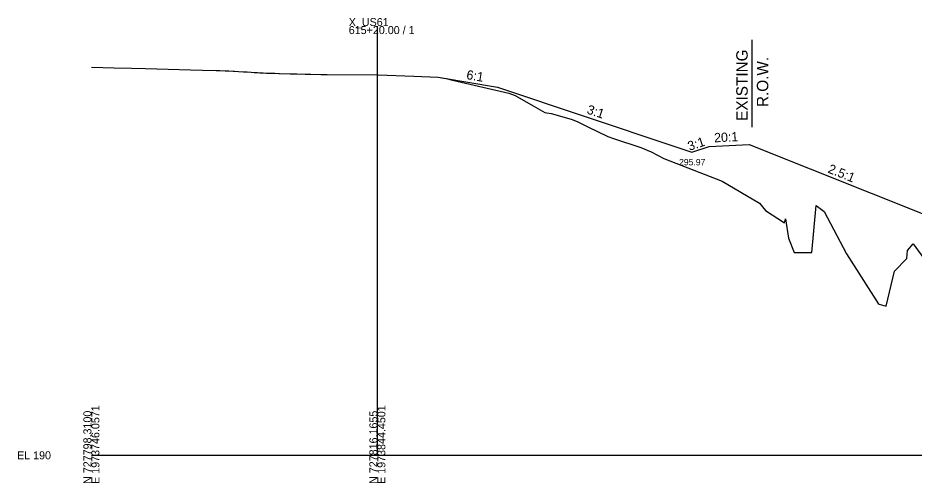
# Model space of a CAD drawing. Extents: x -26 to 1604, y -13 to 9623.
# Drawn here: x -25.7 to 287.7, y 7990.3 to 8152.8 of the extents above; entities that cross this region are included whole.
import ezdxf

# ---------------------------------------------------------------- set-up
doc = ezdxf.new("R2010")
doc.units = 0
for name, color, linetype in [('Draft_XS_Grid', 7, 'Continuous'), ('DTM_X_GROUND', 7, 'Continuous'), ('SLOPE_STAKES_FILL', 7, 'Continuous'), ('XS_CELL', 7, 'Continuous'), ('XS_P_GROUND', 7, 'Continuous'), ('XS_P_TX_DCH', 7, 'Continuous'), ('XS_P_TX_FS_BS', 7, 'Continuous'), ('XS_X_ROW', 7, 'Continuous')]:
    doc.layers.add(name, color=color, linetype=linetype)

msp = doc.modelspace()

# ---------------------------------------------------------------- linework, layer by layer
at = {"layer": 'DTM_X_GROUND'}
msp.add_lwpolyline([(0, 8135.61), (7.94, 8135.42), (14.03, 8135.27), (18.94, 8135.15), (26.84, 8134.94), (34.61, 8134.74), (38.87, 8134.62), (43.59, 8134.47), (44.87, 8134.43), (46.83, 8134.36), (48.09, 8134.33), (49.61, 8134.26), (49.94, 8134.24), (50.08, 8134.23), (51.39, 8134.15), (53.15, 8134.05), (54.01, 8133.98), (54.45, 8133.95), (55.91, 8133.86), (56.88, 8133.8), (58.13, 8133.73), (58.85, 8133.69), (59.52, 8133.66), (60.09, 8133.64), (61.22, 8133.59), (62.07, 8133.56), (64.18, 8133.5), (65.53, 8133.47), (65.75, 8133.46), (69.45, 8133.34), (71.78, 8133.27), (74.79, 8133.24), (76.78, 8133.2), (80.26, 8133.13), (82.47, 8133.08), (100.31, 8132.99), (112.78, 8132.46), (121.22, 8132.1), (123.3, 8131.75), (124, 8131.63), (126.33, 8131.1), (146.02, 8126.55), (148.22, 8125.71), (154.53, 8122.08), (158.6, 8119.75), (160.77, 8119.45), (167.79, 8117.44), (169.9, 8116.61), (173.57, 8114.84), (180.61, 8111.39), (182.56, 8110.73), (192.13, 8107.56), (195.77, 8106.03), (200.22, 8103.7), (206.41, 8101.27), (220.58, 8095.75), (233.67, 8088.11), (235.75, 8085.53), (242.36, 8081.19), (242.7, 8082.68), (243.74, 8075.86), (245.7, 8070.84), (251.88, 8070.93), (253.48, 8087.28), (256.21, 8085.21), (264.05, 8070.38), (275.14, 8053.01), (275.47, 8052.8), (277.89, 8052.14), (280.85, 8064.33), (285.17, 8068.78), (285.35, 8071.54), (287.31, 8073.96), (291.04, 8068.73)], dxfattribs=at)
at = {"layer": 'XS_CELL'}
for p, q in [((100, 8000), (100, 8150)), ((0, 8000), (100, 8000)), ((100, 8000), (600, 8000))]:
    msp.add_line(p, q, dxfattribs=at)
at = {"layer": 'XS_P_GROUND'}
for points in [[(122, 8131.97), (142, 8128.64)], [(142, 8128.64), (204, 8107.97), (210, 8105.97), (216, 8107.97), (230, 8108.67), (294, 8083.07), (300, 8080.67), (306, 8083.07), (320, 8083.77), (384, 8058.17), (390, 8055.77), (396, 8058.17), (410, 8058.87), (415.78, 8056.56)]]:
    msp.add_lwpolyline(points, dxfattribs=at)
at = {"layer": 'XS_X_ROW'}
msp.add_line((231, 8145.19), (231, 8114.65), dxfattribs=at)

# ---------------------------------------------------------------- texts
at = {"layer": 'Draft_XS_Grid'}
msp.add_text('-', height=0.0001, dxfattribs=at).set_placement((0, 8000))
at = {"layer": 'SLOPE_STAKES_FILL'}
for p in [(141.96, 8128.58), (203.96, 8107.91), (215.96, 8107.91), (229.96, 8108.61), (209.96, 8105.91)]:
    msp.add_text('X', height=0.12, dxfattribs=at).set_placement(p)
at = {"layer": 'XS_CELL'}
for s, p in [('X_US61', (90, 8150)), ('615+20.00 / 1', (90, 8147.2)), ('EL 190', (-26, 7998.6))]:
    msp.add_text(s, height=2.8, dxfattribs=at).set_placement(p)
for s, p in [('E 1973746.0571', (2.8, 7990)), ('E 1973844.4501', (102.8, 7990)), ('N 727798.3100', (0, 7990)), ('N 727816.1655', (100, 7990))]:
    msp.add_text(s, height=2.8, rotation=90, dxfattribs=at).set_placement(p)
at = {"layer": 'XS_P_GROUND'}
msp.add_text('X', height=0.12, dxfattribs=at).set_placement((121.96, 8131.91))
at = {"layer": 'XS_P_TX_DCH'}
msp.add_text('295.97', height=2.25, dxfattribs=at).set_placement((205.5, 8101.32))
at = {"layer": 'XS_P_TX_FS_BS'}
for s, rotation, p in [('6:1', 350.5377, (130.96, 8131.49)), ('3:1', 341.5651, (173.01, 8119.52)), ('3:1', 18.4349, (209.13, 8106.37)), ('20:1', 2.8624, (217.83, 8109.36)), ('2.5:1', 338.1986, (257.28, 8098.88))]:
    msp.add_text(s, height=3.24, rotation=rotation, dxfattribs=at).set_placement(p)
at = {"layer": 'XS_X_ROW'}
for s, p in [('EXISTING', (229.5, 8116.86)), ('R.O.W.', (236.7, 8121.7))]:
    msp.add_text(s, height=4, rotation=90, dxfattribs=at).set_placement(p)

doc.saveas('drawing.dxf')
